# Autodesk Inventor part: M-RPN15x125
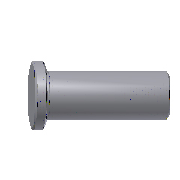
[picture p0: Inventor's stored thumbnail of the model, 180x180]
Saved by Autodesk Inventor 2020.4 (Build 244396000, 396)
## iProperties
Created: 2019-01
Part Number: M-RPN15x125
Material: SUJ 2
Description: Return Pin
Document SubType Name: Modeling
Designer: mel
Standard Revision: 1
Manufacturer: FUTABA
Language: fr-FR
Size Designation: 15x125
Categories: <MemberInstance><Categories><Category DisplayName="Moule" InternalName="349578f2-f4d4-4954-8c09-8e99297a61c0" Mnemonic="MOLD"><Category DisplayName="Composants
Mass: 6.63789 g
Surface Area: 25.7048 cm^2
Volume: 6.63789 cm^3
Density: 7.85 g/cm^3
Appearance: Aluminium - Noir
IsCustomPart: 1
Author: mel
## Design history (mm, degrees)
sketch "Sketch1"
  geometry: L1 (0, -15)-(0, 62) reference; L2 (0, -4)-(10, -4); L3 (10, -4)-(10, 0); L4 (10, 0)-(7.5, 0); L5 (7.5, 0)-(7.5, 121); L6 (7.5, 121)-(0, 121); L7 (0, 121)-(0, -4); 1 further point
  constraints: 12 end point, 3 perpendicular, 2 parallel, 2 point on line, 1 collinear, 1 horizontal alignment
  dimensions: "d28" = 4 distance between parallel lines of L2 L4 (= H_); "d29" = 20 diameter of L3 L1 (= D); "d31" = 15 diameter of L5 L1 (= d_); "d33" = 125 distance between parallel lines of L2 L6 (= L)
revolve "Revolution1" sketch "Sketch1" stored, may be unused: angle "d41" = 90 deg
sketch "Sketch2"
  geometry: L1 (7.5, 121)-(7.5, 0) reference; L2 (-7.5, 0)-(7.5, 0) reference; L3 (7.5, 0)-(7.3, 0); L4 (7, 0.3)-(7, 0.9); L5 (7.3, 1.2)-(7.5, 1.2); L6 (7.5, 1.2)-(7.5, 0); L7 (0, -10.275)-(0, 61.212) reference; A1 r 0.3 centre (7.3, 0.9) between (7.3, 1.2) and (7, 0.9); A2 r 0.3 centre (7.3, 0.3) between (7, 0.3) and (7.3, 0); 1 further point
  constraints: 8 end point, 4 point on circle, 4 tangent, 2 centre point, 2 parallel, 1 equal radius, 1 horizontal, 1 perpendicular
  dimensions: "d45" = 0.3 radius of A1; "d46" = 1.2 distance between parallel lines of L2 L5; "d47" = 0.5 distance between parallel lines of L4 L1
revolve "Revolution2" sketch "Sketch2" stored, may be unused: angle "d48" = 90 deg
chamfer "Chamfer1" distance "d49" = 0.5; stored, may be unused: second distance "d50" = 2, angle "d51" = 45 deg
body "Solid1"
other parameters: "d_" = 15 [user parameter; used in 1 equation term], "L" = 125 [user parameter; used in 1 equation term], "D" = 20 [user parameter; used in 1 equation term], "H_" = 4 [user parameter; used in 1 equation term], "d44" = 0, "d52" = 0, "d53" = 0
